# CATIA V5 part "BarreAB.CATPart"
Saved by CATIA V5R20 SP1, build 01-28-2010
Part number: BarreAB
Bounding box of the stored display mesh (mm): x -30 to 10, y -69.952 to 69.952, z -19.992 to 19.992
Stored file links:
  C:\Documents and Settings\ndumont\Bureau\ndumont_CAO\BarreAB.CATPart
  C:\Documents and Settings\ndumont\Bureau\ndumont_CAO\ndumont.CATProduct
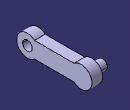
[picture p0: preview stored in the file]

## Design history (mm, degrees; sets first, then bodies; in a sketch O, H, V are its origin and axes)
External parameters (linked from other documents)
  External.DiametrePivotABetDC = 40 mm
  External.LargeurABetDC = 30 mm
  External.DiametreTrousABetDC = 18 mm
  External.EpaisseurABetDC = 20 mm
Set1
  Point1: linked copy from another document
  Line1: linked copy from another document
  Point2: linked copy from another document
Body1 (main body)
  Sketch1 on yz-plane, origin (0, 0, 0), H (0, 1, 0), V (0, 0, 1)
    arc A1 centre (-50, 0) radius 20 from (-36.7712, 15) to (-36.7712, -15) ccw
    arc A2 centre (50, 0) radius 20 from (36.7712, -15) to (36.7712, 15) ccw
    circle A3 centre (-50, 0) radius 9
    reference projected point E1 (-50, 0) from Point2
    reference projected point E2 (50, 0) from Point1
    reference projected point E3 (-50, 0) from Point2
    line L1 (-36.7712, 15) -> (36.7712, 15)
    line L2 (36.7712, -15) -> (-36.7712, -15)
    point P7 (-36.7712, -15)
    reference projected line E4 (-50, 0) -> (50, 0) from Line1
    point P8 (-36.7712, -15)
    radius A3 = 9 {= External.DiametreTrousABetDC /2}
    radius A2 = 20 {= External.DiametrePivotABetDC /2}
    radius A1 = 20 {= External.DiametrePivotABetDC /2}
    distance L1 L2 = 30 {= External.LargeurABetDC}
    concentricity: A1 E1, A2 E2, A3 E3
    horizontal: L1 H, L2 H
    symmetry: L1 L2 E4
    coincidence: P7 P8
  Pad1: profile Sketch1, direction (-1, 0, 0), length 10 {= External.EpaisseurABetDC /2}, mirrored extent
  Sketch2 on end face of Pad1, origin (-10, 0, 0), H (0, -1, 0), V (0, 0, 1)
    circle A1 centre (-50, 0) radius 9
    reference projected point E1 (-50, 0) from Point1
    radius A1 = 9 {= External.DiametreTrousABetDC /2}
    concentricity: A1 E1
  Pad2: profile Sketch2, direction (-1, 0, 0), length 20 {= External.EpaisseurABetDC}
